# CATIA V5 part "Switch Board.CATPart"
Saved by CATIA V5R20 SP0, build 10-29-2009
Part number: sb
Bounding box of the stored display mesh (mm): x -250 to 250, y -47.532 to 172.335, z -355 to 250
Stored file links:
  C:\Users\HP\Downloads\Catia Project\Catia Project\Switch Board.CATPart
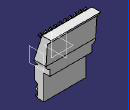
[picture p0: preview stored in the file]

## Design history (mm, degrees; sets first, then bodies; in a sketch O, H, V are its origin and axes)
Body1 (main body)
  Sketch1 on yz-plane, origin (0, 0, 0), H (0, 1, 0), V (0, 0, 1)
    line L1 (0, 0) -> (120.95, 0)
    line L2 (0, 0) -> (82.4376, 250)
    line L3 (82.4376, 250) -> (172.3353, 250)
    line L4 (172.3353, 250) -> (144.6003, 208.3975)
    line L5 (144.6003, 208.3975) -> (134.6003, 208.3975)
    line L6 (134.6003, 208.3975) -> (120.95, 0)
    angle L2 L1 = 71.75
    length L4 = 50
    distance L3 L1 = 250
    angle L4 L3 = 56.31
  Pad1: profile Sketch1, direction (1, 0, 0), length 250, opposite side length 250
  Sketch2 on zx-plane, origin (0, 0, 0), H (-1, 0, 0), V (0, 0, 1)
    projected line E1 (250, 0) -> (-250, 0) from edge [face of Pad1 from Sketch1.L6 | face of Pad1 from Sketch1.L1]
    construction line L1 (210, 85.0102) -> (210, -51.117)
    axis line L2 (-210, 85.0102) -> (-210, -60.1922)
    construction line L3 (-210, 0) -> (210, 0)
    line L4 (210, -40) -> (-210, -40)
    arc A1 centre (210, 0) radius 40 from (250, 0) to (210, -40) cw
    arc A2 centre (-210, 0) radius 40 from (-210, -40) to (-250, 0) cw
    distance L2 V = 210
    distance V L1 = 210
  Pad2: profile Sketch2, direction (0, 1, 0), length 120.95
  Sketch3 on face of Pad1 from Sketch1.L2, origin (0, 0, 0), H (1, 0, 0), V (0, 0.3132, 0.9497)
    axis line L1 (-250, 223.8362) -> (250, 223.8362)
    point P2 (250, 223.8362)
    circle A1 centre (225, 223.8362) radius 13
    point P3 (225, 223.8362)
    distance P3 P2 = 25
  Pad3: profile Sketch3, direction (0, -0.9497, 0.3132), length 40
  Plane1: type Offset, RefPlane yz-plane, Offset 225
  Sketch4 on Plane1, origin (225, 0, 0), H (0, 1, 0), V (0, 0, 1)
    line L1 (59.8386, 197.6173) -> (64.0603, 208.7545)
    line L2 (64.0603, 208.7545) -> (50.0483, 214.066)
    line L3 (50.0483, 214.066) -> (45.8265, 202.9288)
    line L4 (45.8265, 202.9288) -> (59.8386, 197.6173)
  Groove1: profile Sketch4, axis axis of face of Pad3 from Sketch3.A1, angle 360
  Sketch5 on end face of Pad3, origin (0, -37.988, 12.5266), H (1, 0, 0), V (0, 0.3132, 0.9497)
    point P1 (225.6227, 237.5762)
    line L1 (226.3036, 241.7419) -> (226.3036, 233.4105)
    line L2 (226.3036, 233.4105) -> (223.3036, 233.4105)
    line L3 (223.3036, 233.4105) -> (223.3036, 241.7419)
    line L4 (223.3036, 241.7419) -> (226.3036, 241.7419)
    line L5 (217.0304, 229.4067) -> (211.1392, 235.2979)
    line L6 (213.2606, 237.4192) -> (219.1517, 231.528)
    line L7 (219.1517, 231.528) -> (217.0304, 229.4067)
    line L8 (211.1392, 235.2979) -> (213.2606, 237.4192)
    line L9 (215.4257, 222.1398) -> (207.0944, 222.1398)
    line L10 (207.0944, 225.1398) -> (215.4257, 225.1398)
    line L11 (215.4257, 225.1398) -> (215.4257, 222.1398)
    line L12 (207.0944, 222.1398) -> (207.0944, 225.1398)
    line L13 (218.2711, 217.0251) -> (212.3799, 211.1339)
    line L14 (210.2586, 213.2552) -> (216.1498, 219.1464)
    line L15 (216.1498, 219.1464) -> (218.2711, 217.0251)
    line L16 (212.3799, 211.1339) -> (210.2586, 213.2552)
    line L17 (225.0582, 214.262) -> (225.0582, 205.9306)
    line L18 (222.0582, 205.9306) -> (222.0582, 214.262)
    line L19 (222.0582, 214.262) -> (225.0582, 214.262)
    line L20 (225.0582, 205.9306) -> (222.0582, 205.9306)
    line L21 (231.8112, 217.1073) -> (237.7023, 211.2162)
    line L22 (235.581, 209.0949) -> (229.6898, 214.986)
    line L23 (229.6898, 214.986) -> (231.8112, 217.1073)
    line L24 (237.7023, 211.2162) -> (235.581, 209.0949)
    line L25 (234.5743, 223.8944) -> (242.9056, 223.8944)
    line L26 (242.9056, 220.8944) -> (234.5743, 220.8944)
    line L27 (234.5743, 220.8944) -> (234.5743, 223.8944)
    line L28 (242.9056, 223.8944) -> (242.9056, 220.8944)
    line L29 (230.5705, 231.8058) -> (236.4616, 237.697)
    line L30 (238.5829, 235.5757) -> (232.6918, 229.6845)
    line L31 (232.6918, 229.6845) -> (230.5705, 231.8058)
    line L32 (236.4616, 237.697) -> (238.5829, 235.5757)
    distance L1 L3 = 3
    distance L30 L29 = 3
    distance L26 L25 = 3
    distance L21 L22 = 3
    distance L18 L17 = 3
    distance L13 L14 = 3
    distance L9 L10 = 3
    distance L5 L6 = 3
  Pocket1: profile Sketch5, direction (0, 0.9497, -0.3132), length 25
  RectPattern1: of Pad3, Groove1, Pocket1, direction 1 instances 10, spacing 50, along edge [face of Pad1 from Sketch1.L2 | face of Pad1 from Sketch1.L3] reversed
  Sketch6 on face of Pad1 from Sketch1.L2, origin (0, 0, 0), H (1, 0, 0), V (0, 0.3132, 0.9497)
    construction line L1 (-250, 249.8325) -> (250, 249.8325)
    axis line L2 (200, 283.7767) -> (200, 188.4948)
    circle A1 centre (200, 249.8325) radius 5.2759
  Pad4: profile Sketch6, direction (0, -0.9497, 0.3132), length 5
  Sketch7 on end face of Pad4, origin (0, -4.7485, 1.5658), H (1, 0, 0), V (0, 0.3132, 0.9497)
    point P1 (200, 249.8325)
    line L1 (207.6662, 250.8756) -> (207.6662, 248.7895)
    line L2 (207.6662, 248.7895) -> (201.275, 248.7895)
    line L3 (192.3338, 248.7895) -> (192.3338, 250.8756)
    line L4 (192.3338, 250.8756) -> (198.725, 250.8756)
    line L5 (201.275, 256.9655) -> (201.275, 250.8756)
    line L6 (201.275, 242.6995) -> (198.725, 242.6995)
    line L7 (198.725, 242.6995) -> (198.725, 248.7895)
    line L8 (198.725, 256.9655) -> (201.275, 256.9655)
    line L9 (198.725, 248.7895) -> (192.3338, 248.7895)
    line L10 (201.275, 248.7895) -> (201.275, 242.6995)
    line L11 (201.275, 250.8756) -> (207.6662, 250.8756)
    line L12 (198.725, 250.8756) -> (198.725, 256.9655)
  Pocket2: profile Sketch7, direction (0, 0.9497, -0.3132), length 2.5
  RectPattern2: of Pad4, Pocket2, direction 1 instances 9, spacing 50, along edge [face of Pad1 from Sketch1.L2 | face of Pad1 from Sketch1.L3] reversed
  Sketch8 on face of Pad1 from Sketch1.L2, origin (0, 0, 0), H (1, 0, 0), V (0, 0.3132, 0.9497)
    axis line L1 (-250, 176.7381) -> (250, 176.7381)
    circle A1 centre (225, 176.7381) radius 13
    circle A2 centre (225, 176.7381) radius 10.7107
    radius A1 = 13
  Pad5: profile Sketch8, direction (0, -0.9497, 0.3132), length 2.5
  RectPattern3: of Pad5, direction 1 instances 10, spacing 50, along edge [face of Pad1 from Sketch1.L2 | face of Pad1 from Sketch1.L3] reversed
  Sketch9 on face of Pad1 from Sketch1.L2, origin (0, 0, 0), H (1, 0, 0), V (0, 0.3132, 0.9497)
    axis line L1 (-250, 96.3563) -> (250, 96.3563)
    circle A1 centre (225, 96.3563) radius 17.5
    circle A2 centre (225, 96.3563) radius 11.0678
    radius A1 = 17.5
  Pad6: profile Sketch9, direction (0, -0.9497, 0.3132), length 7
  RectPattern4: of Pad6, direction 1 instances 10, spacing 50, along edge [face of Pad1 from Sketch1.L2 | face of Pad1 from Sketch1.L3] reversed
  Sketch10 on face of Pad1 from Sketch1.L2, origin (0, 0, 0), H (1, 0, 0), V (0, 0.3132, 0.9497)
    circle A1 centre (200, 47.1426) radius 17.5
    point P1 (200, 47.1426)
    reference projected line E1 (250, 263.2413) -> (250, 0) from edge [face of Pad1 from Sketch1.L2 | end face of Pad1]
    circle A2 centre (200, 47.1426) radius 9.3837
    radius A1 = 17.5
    distance P1 E1 = 50
  Pad7: profile Sketch10, direction (0, -0.9497, 0.3132), length 5
  RectPattern5: of Pad7, direction 1 instances 9, spacing 50, along edge [face of Pad1 from Sketch1.L2 | face of Pad1 from Sketch1.L3] reversed
  Sketch11 on face of Pad2 from Sketch2.L4, origin (0, 0, -40), H (1, 0, 0), V (0, -1, 0)
  Pad8: profile Sketch11, direction (0, 0, -1), length 315
  Sketch12 on face of Pad8, origin (210, 0, 0), H (0, 1, 0), V (0, 0, 1)
    projected line E1 (0, -40) -> (120.95, -40) from edge [face of Pad8 | face of Pad2 from Sketch2.A2]
    line L1 (120.95, -40) -> (120.95, -55.4691)
    line L2 (120.95, -55.4691) -> (-31.05, -55.4691)
    line L3 (-31.05, -55.4691) -> (-31.05, -40)
    line L4 (-31.05, -40) -> (0, -40)
  Pad9: profile Sketch12, direction (-1, 0, 0), up to face of Pad8
  Sketch13 on face of Pad8, origin (210, 0, 0), H (0, 1, 0), V (0, 0, 1)
    line L1 (120.95, -355) -> (60.95, -355)
    line L2 (60.95, -355) -> (60.95, -105)
    line L3 (60.95, -105) -> (120.95, -105)
    line L4 (120.95, -105) -> (120.95, -355)
    reference projected line E1 (120.95, -40) -> (0, -40) from edge [face of Pad2 from Sketch2.A2 | face of Pad8]
    distance L3 E1 = 65
    distance L2 L4 = 60
  Pocket3: profile Sketch13, direction (-1, 0, 0), up to face of Pad8
  Sketch14 on face of Pad8, origin (-210, 0, 0), H (0, -1, 0), V (0, 0, 1)
    projected line E1 (0, -55.4691) -> (0, -355) from edge [face of Pad8 | face of Pad8]
    projected line E2 (0, -65.9444) -> (0, -229.1832) from edge [face of Pad8 | face of Pad8]
    construction line L1 (0, -98.2989) -> (0, -196.8287)
    line L2 (32.3545, -98.2989) -> (32.3545, -196.8287)
    arc A1 centre (0, -196.8287) radius 32.3545 from (32.3545, -196.8287) to (0, -229.1832) cw
    arc A2 centre (0, -98.2989) radius 32.3545 from (0, -65.9444) to (32.3545, -98.2989) cw
  Pad10: profile Sketch14, direction (1, 0, 0), length 25
  Mirror1: of Pad10, about yz-plane
  Sketch15 on face of Pad10, origin (-210, 0, 0), H (0, -1, 0), V (0, 0, 1)
    line L1 (-11.5701, -346.18) -> (24.5149, -346.18)
    line L2 (24.5149, -346.18) -> (24.5149, -337.8057)
    line L3 (24.5149, -337.8057) -> (5.2136, -331.1063)
    line L4 (5.2136, -331.1063) -> (-11.5701, -331.1063)
    line L5 (-11.5701, -331.1063) -> (-11.5701, -346.18)
    point P6 (-5.95, -284.2105)
    line L6 (32.0676, -269.9742) -> (32.0676, -298.4467)
    line L7 (32.0676, -298.4467) -> (-46.8158, -298.4467)
    line L8 (-46.8158, -298.4467) -> (-46.8158, -269.9742)
    line L9 (-46.8158, -269.9742) -> (32.0676, -269.9742)
    reference projected line E1 (-60.95, -355) -> (-60.95, -105) from edge [face of Pad8 | face of Pocket3 from Sketch13.L2]
    distance P6 E1 = 55
  Pad11: profile Sketch15, direction (1, 0, 0), up to face of Mirror1
  Fillet1: radius 25, on edge [face of Pad11 from Sketch15.L6 | face of Pad10]
  Fillet2: radius 25, on edge [face of Pad11 from Sketch15.L6 | face of Mirror1]
  Sketch16 on face of Pad11 from Sketch15.L9, origin (0, 0, -269.9742), H (1, 0, 0), V (0, 1, 0)
    circle A1 centre (165, -14.9036) radius 8.5
    point P1 (165, -14.9036)
    circle A2 centre (119.0665, -14.9036) radius 8.5
    circle A3 centre (61.1759, -14.9036) radius 8.5
    circle A4 centre (3.2853, -14.9036) radius 8.5
    circle A5 centre (-54.6053, -14.9036) radius 8.5
    circle A6 centre (-112.4959, -14.9036) radius 8.5
    point P7 (-165, -14.9036)
    circle A7 centre (-165, -14.9036) radius 8.5
    circle A8 centre (165, -14.9036) radius 4.7406
    circle A9 centre (119.0665, -14.9036) radius 5.1805
    circle A10 centre (61.1759, -14.9036) radius 5.1946
    circle A11 centre (3.2853, -14.9036) radius 5.0548
    circle A12 centre (-54.6053, -14.9036) radius 5.6259
    circle A13 centre (-112.4959, -14.9036) radius 5.6666
    circle A14 centre (-165, -14.9036) radius 4.5513
    radius A1 = 8.5
    distance P7 P1 = 330
    distance P7 V = 165
  Pad12: profile Sketch16, direction (0, 0, 1), length 25
  Shell1: IntOffset 1, Face end face of Pad12, ExtOffset 0, deactivated
  Sketch17 on face of Pad11 from Sketch15.L1, origin (0, 0, -346.18), H (1, 0, 0), V (0, -1, 0)
    circle A1 centre (175.2575, 12.1307) radius 5.6167
    circle A2 centre (117.759, 12.1307) radius 5.6167
    circle A3 centre (60.2605, 12.1307) radius 5.6167
    circle A4 centre (2.7621, 12.1307) radius 5.6167
    circle A5 centre (-54.7364, 12.1307) radius 5.6167
    circle A6 centre (-112.2349, 12.1307) radius 5.6167
    circle A7 centre (-169.7333, 12.1307) radius 5.6167
  Pocket4: profile Sketch17, direction (0, 0, 1), length 25
  Sketch18 on face of Mirror1, origin (185, 0, 0), H (0, -1, 0), V (0, 0, 1)
    construction line L1 (0, -82.539) -> (0, -156.2164)
    line L2 (15.9634, -82.539) -> (15.9634, -156.2164)
    arc A1 centre (0, -156.2164) radius 15.9634 from (15.9634, -156.2164) to (0, -172.1798) cw
    arc A2 centre (0, -82.539) radius 15.9634 from (0, -66.5756) to (15.9634, -82.539) cw
    line L3 (0, -66.5756) -> (0, -172.1798)
  Pad13: profile Sketch18, direction (-1, 0, 0), up to end face of Pad10
  Sketch19 on face of Pad13 from Sketch18.L2, origin (0, -15.9634, 0), H (1, 0, 0), V (0, 0, 1)
    point P1 (166.6781, -107.8214)
    line L1 (169.5438, -57.7264) -> (169.5438, -157.9165)
    line L2 (165.5438, -157.9165) -> (165.5438, -57.7264)
    line L3 (165.5438, -57.7264) -> (169.5438, -57.7264)
    arc A1 centre (167.5438, -161.7161) radius 4.2938 from (165.5438, -157.9165) to (169.5438, -157.9165) ccw
    line L4 (145.7382, -157.9165) -> (145.7382, -57.7264)
    line L5 (149.7382, -57.7264) -> (149.7382, -157.9165)
    arc A2 centre (147.7382, -161.7161) radius 4.2938 from (145.7382, -157.9165) to (149.7382, -157.9165) ccw
    line L6 (145.7382, -57.7264) -> (149.7382, -57.7264)
    line L7 (125.9325, -157.9165) -> (125.9325, -57.7264)
    line L8 (129.9325, -57.7264) -> (129.9325, -157.9165)
    arc A3 centre (127.9325, -161.7161) radius 4.2938 from (125.9325, -157.9165) to (129.9325, -157.9165) ccw
    line L9 (125.9325, -57.7264) -> (129.9325, -57.7264)
    line L10 (106.1268, -157.9165) -> (106.1268, -57.7264)
    line L11 (110.1268, -57.7264) -> (110.1268, -157.9165)
    arc A4 centre (108.1268, -161.7161) radius 4.2938 from (106.1268, -157.9165) to (110.1268, -157.9165) ccw
    line L12 (106.1268, -57.7264) -> (110.1268, -57.7264)
    line L13 (86.3211, -157.9165) -> (86.3211, -57.7264)
    line L14 (90.3211, -57.7264) -> (90.3211, -157.9165)
    arc A5 centre (88.3211, -161.7161) radius 4.2938 from (86.3211, -157.9165) to (90.3211, -157.9165) ccw
    line L15 (86.3211, -57.7264) -> (90.3211, -57.7264)
    line L16 (66.5154, -157.9165) -> (66.5154, -57.7264)
    line L17 (70.5154, -57.7264) -> (70.5154, -157.9165)
    arc A6 centre (68.5154, -161.7161) radius 4.2938 from (66.5154, -157.9165) to (70.5154, -157.9165) ccw
    line L18 (66.5154, -57.7264) -> (70.5154, -57.7264)
    line L19 (46.7097, -157.9165) -> (46.7097, -57.7264)
    line L20 (50.7097, -57.7264) -> (50.7097, -157.9165)
    arc A7 centre (48.7097, -161.7161) radius 4.2938 from (46.7097, -157.9165) to (50.7097, -157.9165) ccw
    line L21 (46.7097, -57.7264) -> (50.7097, -57.7264)
    line L22 (26.904, -157.9165) -> (26.904, -57.7264)
    line L23 (30.904, -57.7264) -> (30.904, -157.9165)
    arc A8 centre (28.904, -161.7161) radius 4.2938 from (26.904, -157.9165) to (30.904, -157.9165) ccw
    line L24 (26.904, -57.7264) -> (30.904, -57.7264)
    line L25 (7.0984, -157.9165) -> (7.0984, -57.7264)
    line L26 (11.0984, -57.7264) -> (11.0984, -157.9165)
    arc A9 centre (9.0984, -161.7161) radius 4.2938 from (7.0984, -157.9165) to (11.0984, -157.9165) ccw
    line L27 (7.0984, -57.7264) -> (11.0984, -57.7264)
    line L28 (-12.7073, -157.9165) -> (-12.7073, -57.7264)
    line L29 (-8.7073, -57.7264) -> (-8.7073, -157.9165)
    arc A10 centre (-10.7073, -161.7161) radius 4.2938 from (-12.7073, -157.9165) to (-8.7073, -157.9165) ccw
    line L30 (-12.7073, -57.7264) -> (-8.7073, -57.7264)
    line L31 (-32.513, -157.9165) -> (-32.513, -57.7264)
    line L32 (-28.513, -57.7264) -> (-28.513, -157.9165)
    arc A11 centre (-30.513, -161.7161) radius 4.2938 from (-32.513, -157.9165) to (-28.513, -157.9165) ccw
    line L33 (-32.513, -57.7264) -> (-28.513, -57.7264)
    line L34 (-52.3187, -157.9165) -> (-52.3187, -57.7264)
    line L35 (-48.3187, -57.7264) -> (-48.3187, -157.9165)
    arc A12 centre (-50.3187, -161.7161) radius 4.2938 from (-52.3187, -157.9165) to (-48.3187, -157.9165) ccw
    line L36 (-52.3187, -57.7264) -> (-48.3187, -57.7264)
    line L37 (-72.1244, -157.9165) -> (-72.1244, -57.7264)
    line L38 (-68.1244, -57.7264) -> (-68.1244, -157.9165)
    arc A13 centre (-70.1244, -161.7161) radius 4.2938 from (-72.1244, -157.9165) to (-68.1244, -157.9165) ccw
    line L39 (-72.1244, -57.7264) -> (-68.1244, -57.7264)
    line L40 (-91.9301, -157.9165) -> (-91.9301, -57.7264)
    line L41 (-87.9301, -57.7264) -> (-87.9301, -157.9165)
    arc A14 centre (-89.9301, -161.7161) radius 4.2938 from (-91.9301, -157.9165) to (-87.9301, -157.9165) ccw
    line L42 (-91.9301, -57.7264) -> (-87.9301, -57.7264)
    line L43 (-111.7358, -157.9165) -> (-111.7358, -57.7264)
    line L44 (-107.7358, -57.7264) -> (-107.7358, -157.9165)
    arc A15 centre (-109.7358, -161.7161) radius 4.2938 from (-111.7358, -157.9165) to (-107.7358, -157.9165) ccw
    line L45 (-111.7358, -57.7264) -> (-107.7358, -57.7264)
    line L46 (-131.5414, -157.9165) -> (-131.5414, -57.7264)
    line L47 (-127.5414, -57.7264) -> (-127.5414, -157.9165)
    arc A16 centre (-129.5414, -161.7161) radius 4.2938 from (-131.5414, -157.9165) to (-127.5414, -157.9165) ccw
    line L48 (-131.5414, -57.7264) -> (-127.5414, -57.7264)
    line L49 (-151.3471, -157.9165) -> (-151.3471, -57.7264)
    line L50 (-147.3471, -57.7264) -> (-147.3471, -157.9165)
    arc A17 centre (-149.3471, -161.7161) radius 4.2938 from (-151.3471, -157.9165) to (-147.3471, -157.9165) ccw
    line L51 (-151.3471, -57.7264) -> (-147.3471, -57.7264)
    line L52 (-171.1528, -157.9165) -> (-171.1528, -57.7264)
    line L53 (-167.1528, -57.7264) -> (-167.1528, -157.9165)
    arc A18 centre (-169.1528, -161.7161) radius 4.2938 from (-171.1528, -157.9165) to (-167.1528, -157.9165) ccw
    line L54 (-171.1528, -57.7264) -> (-167.1528, -57.7264)
    distance L2 L1 = 4
  Pocket5: profile Sketch19, direction (0, 1, 0), length 30
  Sketch20 on face of Pocket5 from Sketch19.L52, origin (-171.1528, 0, 0), H (0, 1, 0), V (0, 0, 1)
    spline S1 through (12.26, -58.3295) (-18.667, -58.3295) (-47.5322, -69.3027)
    spline S2 through (12.26, -61.8795) (-18.667, -61.8795) (-45.6229, -70.59)
    line L1 (-47.5322, -69.3027) -> (-45.6229, -70.59)
    point P1 (-47.5322, -69.3027)
    point P2 (-45.6229, -70.59)
    line L2 (12.26, -58.3295) -> (12.26, -61.8795)
    point P3 (12.26, -58.3295)
    point P4 (12.26, -61.8795)
    point P5 (-47.5322, -69.3027)
    point P6 (-45.6229, -70.59)
    point P7 (12.26, -58.3295)
    point P8 (12.26, -61.8795)
    coincidence: P5 P1, P6 P2, P7 P3, P8 P4
  Pad14: profile Sketch20, direction (1, 0, 0), length 4
  RectPattern6: of Pad14, direction 1 instances 18, spacing 19.806, along edge [face of Pad8 | face of Pad9 from Sketch12.L2]
  Set1 "Extracted Geometry (Shell.1)"
    Extract1: ExtractElem end face of Pad12
  Pad15: profile Sketch5, direction (0, -0.9497, 0.3132), length 250, opposite side length 250
Current feature: RectPattern6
